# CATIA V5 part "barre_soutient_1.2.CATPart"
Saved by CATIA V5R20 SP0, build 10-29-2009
Part number: barre_soutient_1.2
Bounding box of the stored display mesh (mm): x 460.778 to 500.778, y -642.675 to 190.07, z -653.589 to -33.75
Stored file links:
  C:\Users\Mike-7\Desktop\MMS_GR3\bfoltzer\CFAO_bfoltzer\barre_soutient_1.2.CATPart
  D:\ecole\thinkmotion\Eolienne.CATProduct
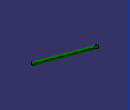
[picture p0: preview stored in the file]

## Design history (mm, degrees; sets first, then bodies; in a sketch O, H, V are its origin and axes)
Set1
  Plane1 "plan de bout de barre": linked copy from another document
  Point1: linked copy from another document
  Point2: linked copy from another document
  Plane2 "Plan de bout de barre": linked copy from another document
Body1 (main body)
  Sketch1 on Plane1, origin (0, 24.976, 161.2989), H (1, 0, 0), V (0, -0.5875, 0.8092)
    circle A1 centre (480.7782, -261.0253) radius 20
    point P1 (480.7782, -261.0253)
    reference projected point E1 (480.7782, -261.0253) from Point1
    reference projected point E2 (460.7782, -261.0253) from Point2
    coincidence: P1 E1, A1 E2
  Pad1: profile Sketch1, direction (0, -0.8092, -0.5875), up to Plane2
